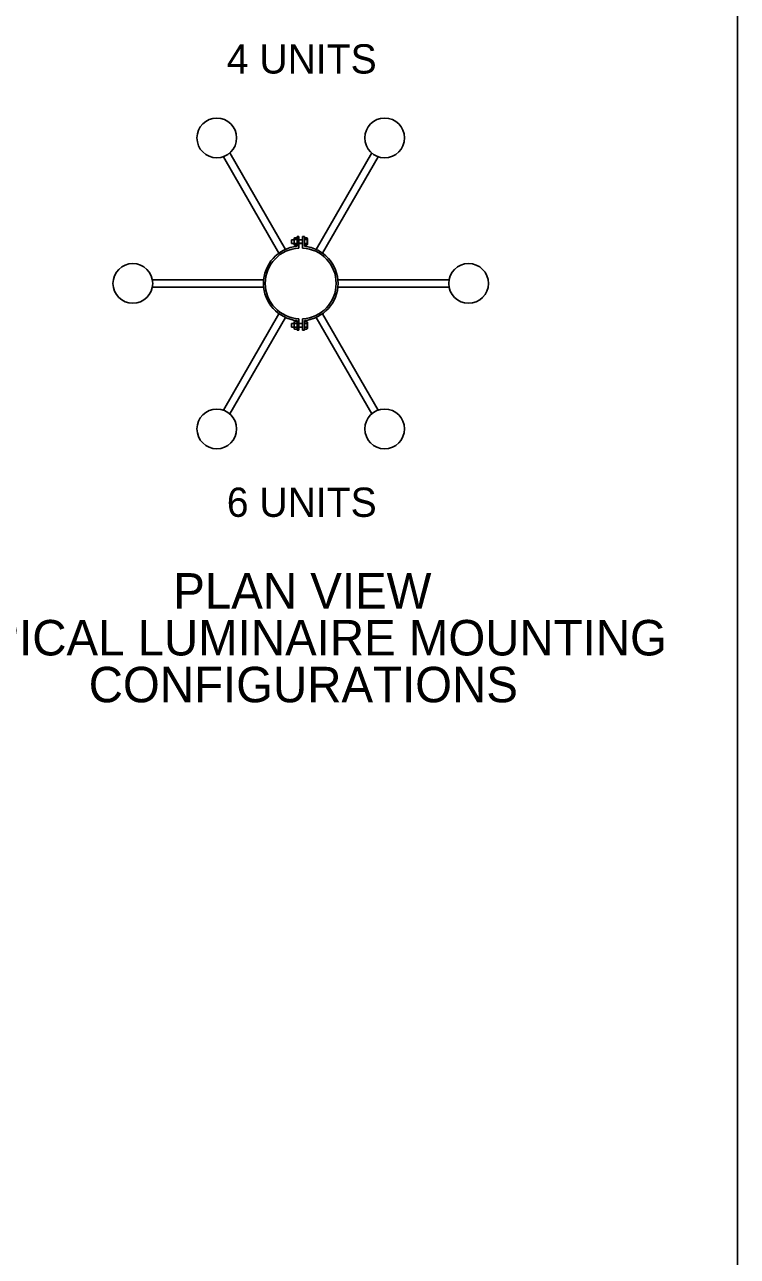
# Model space of a CAD drawing. Extents: x 99862 to 104211, y 98939 to 102076.
# Drawn here: x 102749 to 103151, y 100507 to 101202 of the extents above; entities that cross this region are included whole.
import ezdxf

# ---------------------------------------------------------------- set-up
doc = ezdxf.new("R2010")
doc.units = 0
for name, color, linetype in [('Level 1', 7, 'Continuous'), ('Level 2', 7, 'Continuous'), ('Level 20', 7, 'Continuous'), ('Level 4', 7, 'Continuous'), ('Level 7', 7, 'Continuous')]:
    doc.layers.add(name, color=color, linetype=linetype)

msp = doc.modelspace()

# ---------------------------------------------------------------- linework, layer by layer
at = {"layer": 'Level 1'}
msp.add_lwpolyline([(99862, 99999.5), (103151, 99999.5), (103151, 102075.5), (99862, 102075.5)], close=True, dxfattribs=at)
at = {"layer": 'Level 2'}
for p, q in [((102902.53, 101082.46), (102903.56, 101082.46)), ((102902.53, 101077.02), (102902.53, 101082.46)), ((102902.53, 101080.76), (102902.53, 101078.69)), ((102903.56, 101082.46), (102903.56, 101076.06)), ((102903.56, 101078.69), (102903.56, 101080.76)), ((102905.64, 101076.06), (102905.64, 101082.46)), ((102905.64, 101082.46), (102906.68, 101082.46)), ((102905.64, 101080.76), (102905.64, 101078.69)), ((102906.68, 101082.46), (102906.68, 101077.02)), ((102902.53, 101078.68), (102902.53, 101078.69)), ((102903.56, 101078.69), (102903.56, 101078.68)), ((102903.56, 101078.69), (102903.56, 101078.68)), ((102902.53, 101029.72), (102902.53, 101035.15)), ((102903.56, 101036.11), (102903.56, 101029.72)), ((102905.64, 101029.72), (102905.64, 101036.11)), ((102906.68, 101035.15), (102906.68, 101029.72)), ((102903.56, 101029.72), (102902.53, 101029.72)), ((102906.68, 101029.72), (102905.64, 101029.72))]:
    msp.add_line(p, q, dxfattribs=at)
for radius, start, end in [(21.04, 95.66048, 264.33952), (20, 92.97355, 267.02645), (20, 272.97355, 87.02645), (21.04, 275.66048, 84.33952)]:
    msp.add_arc((102904.6, 101056.09), radius, start, end, dxfattribs=at)
at = {"layer": 'Level 4'}
for p, q in [((102895.93, 101075.25), (102864.53, 101129.64)), ((102944.67, 101129.64), (102913.27, 101075.25)), ((102860.94, 101127.56), (102892.34, 101073.18)), ((102916.87, 101073.18), (102948.26, 101127.56)), ((102883.67, 101058.16), (102820.87, 101058.16)), ((102820.87, 101054.01), (102883.67, 101054.01)), ((102988.33, 101058.16), (102925.54, 101058.16)), ((102925.54, 101054.01), (102988.33, 101054.01)), ((102892.34, 101038.99), (102860.94, 100984.61)), ((102948.26, 100984.61), (102916.87, 101038.99)), ((102864.53, 100982.54), (102895.93, 101036.92)), ((102913.27, 101036.92), (102944.67, 100982.54))]:
    msp.add_line(p, q, dxfattribs=at)
for centre in [(102857.24, 101138.13), (102951.97, 101138.13), (102809.87, 101056.09), (102999.33, 101056.09), (102857.24, 100974.05), (102951.97, 100974.05)]:
    msp.add_circle(centre, 11.2, dxfattribs=at)
at = {"layer": 'Level 7'}
for p, q in [((102899.39, 101080.75), (102899.39, 101078.7)), ((102899.39, 101080.75), (102899.39, 101078.7)), ((102900.87, 101080.75), (102899.39, 101080.75)), ((102901.14, 101081.81), (102900.87, 101081.5)), ((102900.87, 101081.5), (102900.87, 101077.96)), ((102900.87, 101077.96), (102900.87, 101081.5)), ((102900.87, 101077.96), (102900.87, 101081.5)), ((102900.87, 101077.96), (102900.87, 101081.49)), ((102900.87, 101080.75), (102900.87, 101078.7)), ((102900.87, 101080.75), (102900.87, 101078.7)), ((102900.87, 101080.74), (102900.87, 101078.69)), ((102901.14, 101081.81), (102902.53, 101081.81)), ((102901.14, 101080.77), (102902.53, 101080.77)), ((102905.64, 101080.75), (102903.56, 101080.75)), ((102908.06, 101081.81), (102906.68, 101081.81)), ((102908.06, 101080.77), (102906.68, 101080.77)), ((102908.34, 101081.5), (102908.06, 101081.81)), ((102908.34, 101081.5), (102908.34, 101077.96)), ((102908.34, 101077.96), (102908.34, 101081.5)), ((102908.34, 101077.96), (102908.34, 101081.5)), ((102908.34, 101077.96), (102908.34, 101081.49)), ((102899.39, 101078.7), (102899.39, 101078.69)), ((102899.39, 101078.7), (102899.39, 101078.69)), ((102899.39, 101078.7), (102899.39, 101078.7)), ((102899.39, 101078.69), (102899.39, 101078.69)), ((102899.39, 101078.69), (102900.87, 101078.69)), ((102900.87, 101077.96), (102901.14, 101077.64)), ((102901.14, 101078.69), (102902.53, 101078.69)), ((102901.14, 101077.64), (102902.53, 101077.64)), ((102902.53, 101077.64), (102902.53, 101077.63)), ((102903.56, 101078.7), (102905.64, 101078.7)), ((102903.56, 101078.69), (102905.64, 101078.69)), ((102908.06, 101078.69), (102906.68, 101078.69)), ((102908.06, 101077.64), (102906.68, 101077.64)), ((102908.06, 101077.64), (102908.34, 101077.96)), ((102899.39, 101033.48), (102899.39, 101033.47)), ((102899.39, 101033.48), (102899.39, 101033.47)), ((102900.87, 101033.48), (102899.39, 101033.48)), ((102899.39, 101033.47), (102899.39, 101031.42)), ((102899.39, 101033.47), (102899.39, 101031.42)), ((102899.39, 101031.42), (102899.39, 101031.42)), ((102899.39, 101031.42), (102900.87, 101031.42)), ((102901.14, 101034.53), (102900.87, 101034.22)), ((102900.87, 101030.68), (102900.87, 101034.22)), ((102900.87, 101034.22), (102900.87, 101030.68)), ((102900.87, 101033.48), (102900.87, 101031.43)), ((102900.87, 101033.47), (102900.87, 101031.42)), ((102900.87, 101033.47), (102900.87, 101031.42)), ((102900.87, 101030.68), (102901.14, 101030.36)), ((102901.14, 101034.53), (102902.53, 101034.53)), ((102901.14, 101033.49), (102902.53, 101033.49)), ((102901.14, 101031.41), (102902.53, 101031.41)), ((102905.64, 101033.48), (102903.56, 101033.48)), ((102903.56, 101031.42), (102905.64, 101031.42)), ((102908.06, 101034.53), (102906.68, 101034.53)), ((102908.06, 101033.49), (102906.68, 101033.49)), ((102908.06, 101031.41), (102906.68, 101031.41)), ((102908.34, 101034.22), (102908.06, 101034.53)), ((102908.06, 101030.36), (102908.34, 101030.68)), ((102908.34, 101034.22), (102908.34, 101030.68)), ((102908.34, 101030.68), (102908.34, 101034.22)), ((102908.34, 101030.68), (102908.34, 101034.22)), ((102901.14, 101030.36), (102902.53, 101030.36)), ((102908.06, 101030.36), (102906.68, 101030.36))]:
    msp.add_line(p, q, dxfattribs=at)
for points in [[(102901.14, 101081.81), (102901.07, 101081.73), (102901.01, 101081.64), (102900.92, 101081.47), (102900.9, 101081.38), (102900.9, 101081.11), (102901, 101080.93), (102901.14, 101080.77)], [(102901.14, 101078.69), (102901.07, 101078.85), (102901.01, 101079.02), (102900.92, 101079.37), (102900.9, 101079.54), (102900.9, 101079.91), (102900.92, 101080.09), (102901.01, 101080.43), (102901.07, 101080.6), (102901.14, 101080.77)], [(102908.06, 101081.81), (102908.14, 101081.73), (102908.2, 101081.64), (102908.28, 101081.47), (102908.31, 101081.38), (102908.31, 101081.11), (102908.21, 101080.93), (102908.06, 101080.77)], [(102908.06, 101078.69), (102908.14, 101078.85), (102908.2, 101079.02), (102908.28, 101079.37), (102908.31, 101079.54), (102908.31, 101079.91), (102908.28, 101080.09), (102908.2, 101080.43), (102908.14, 101080.6), (102908.06, 101080.77)], [(102901.14, 101078.69), (102901.07, 101078.6), (102901.01, 101078.52), (102900.92, 101078.35), (102900.9, 101078.25), (102900.9, 101077.99), (102901, 101077.81), (102901.14, 101077.64)], [(102908.06, 101078.69), (102908.14, 101078.6), (102908.2, 101078.52), (102908.28, 101078.35), (102908.31, 101078.25), (102908.31, 101077.99), (102908.21, 101077.81), (102908.06, 101077.64)], [(102901.14, 101034.53), (102901.07, 101034.45), (102901.01, 101034.36), (102900.92, 101034.19), (102900.9, 101034.1), (102900.9, 101033.83), (102901, 101033.65), (102901.14, 101033.49)], [(102901.14, 101031.41), (102901.07, 101031.57), (102901.01, 101031.74), (102900.92, 101032.09), (102900.9, 101032.26), (102900.9, 101032.63), (102900.92, 101032.81), (102901.01, 101033.15), (102901.07, 101033.32), (102901.14, 101033.49)], [(102901.14, 101031.41), (102901.07, 101031.32), (102901.01, 101031.24), (102900.92, 101031.07), (102900.9, 101030.97), (102900.9, 101030.71), (102901, 101030.53), (102901.14, 101030.36)], [(102908.06, 101034.53), (102908.14, 101034.45), (102908.2, 101034.36), (102908.28, 101034.19), (102908.31, 101034.1), (102908.31, 101033.83), (102908.21, 101033.65), (102908.06, 101033.49)], [(102908.06, 101031.41), (102908.14, 101031.57), (102908.2, 101031.74), (102908.28, 101032.09), (102908.31, 101032.26), (102908.31, 101032.63), (102908.28, 101032.81), (102908.2, 101033.15), (102908.14, 101033.32), (102908.06, 101033.49)], [(102908.06, 101031.41), (102908.14, 101031.32), (102908.2, 101031.24), (102908.28, 101031.07), (102908.31, 101030.97), (102908.31, 101030.71), (102908.21, 101030.53), (102908.06, 101030.36)]]:
    msp.add_open_spline(points, degree=3, dxfattribs=at)

# ---------------------------------------------------------------- texts
at = {"layer": 'Level 20'}
for s, height, p in [('4 UNITS', 16.5, (102862.89, 101174.45)), ('6 UNITS', 16.5, (102862.89, 100924.45)), ('PLAN VIEW', 20, (102832.68, 100872.71)), ('TYPICAL LUMINAIRE MOUNTING', 20, (102693.67, 100846.3)), ('CONFIGURATIONS', 20, (102784.97, 100819.88))]:
    msp.add_text(s, height=height, dxfattribs=at).set_placement(p)

doc.saveas('drawing.dxf')
